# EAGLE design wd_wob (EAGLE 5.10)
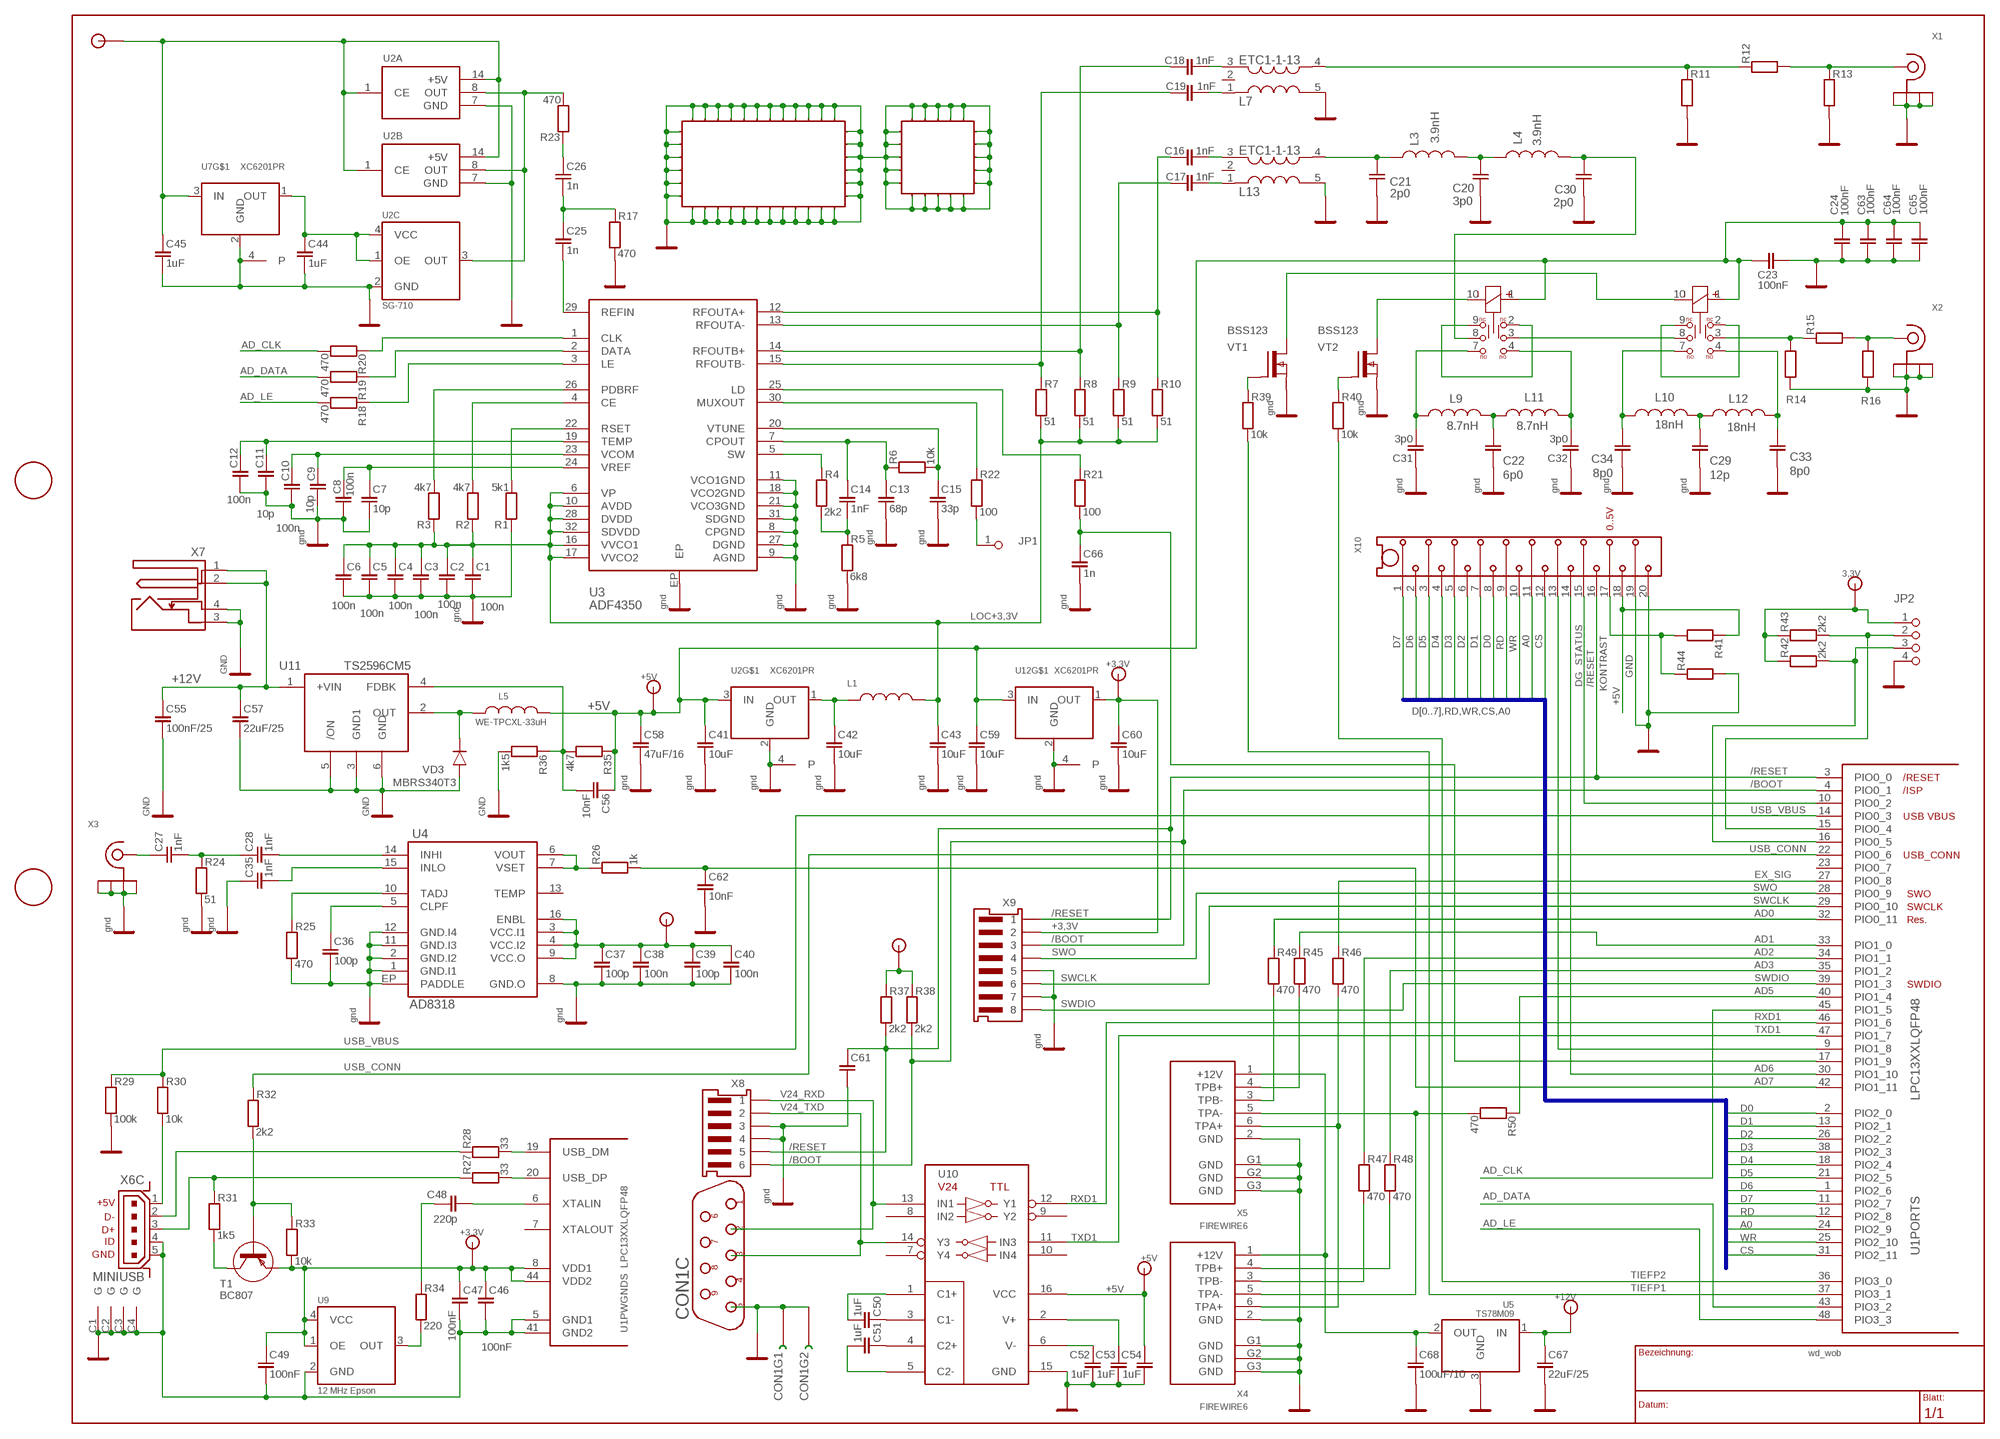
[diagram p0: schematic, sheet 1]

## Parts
C1  100n  SMD-0603  [SOT-0603]
C2  100n  SMD-0603  [SOT-0603]
C3  100n  SMD-0603  [SOT-0603]
C4  100n  SMD-0603  [SOT-0603]
C5  100n  SMD-0603  [SOT-0603]
C6  100n  SMD-0603  [SOT-0603]
C7  10p  SMD-0603  [SOT-0603]
C8  100n  SMD-0603  [SOT-0603]
C9  10p  SMD-0603  [SOT-0603]
C10  100n  SMD-0603  [SOT-0603]
C11  10p  SMD-0603  [SOT-0603]
C12  100n  SMD-0603  [SOT-0603]
C13  68p  SMD-0603  [SOT-0603]
C14  1nF  SMD-0603  [SOT-0603]
C15  33p  SMD-0603  [SOT-0603]
C16  1nF  SMD-0603  [SOT-0603]
C17  1nF  SMD-0603  [SOT-0603]
C18  1nF  SMD-0603  [SOT-0603]
C19  1nF  SMD-0603  [SOT-0603]
C20  3p0  SMD-0603  [SOT-0603]
C21  2p0  SMD-0603  [SOT-0603]
C22  6p0  SMD-0603  [SOT-0603]
C23  100nF  SMD-0603  [SOT-0603]
C24  100nF  SMD-0603  [SOT-0603]
C25  1n  SMD-0603  [SOT-0603]
C26  1n  SMD-0603  [SOT-0603]
C27  1nF  SMD-0603  [SOT-0603]
C28  1nF  SMD-0603  [SOT-0603]
C29  12p  SMD-0603  [SOT-0603]
C30  2p0  SMD-0603  [SOT-0603]
C31  3p0  SMD-0603  [SOT-0603]
C32  3p0  SMD-0603  [SOT-0603]
C33  8p0  SMD-0603  [SOT-0603]
C34  8p0  SMD-0603  [SOT-0603]
C35  1nF  SMD-0603  [SOT-0603]
C36  100p  SMD-0603  [SOT-0603]
C37  100p  SMD-0603  [SOT-0603]
C38  100n  SMD-0603  [SOT-0603]
C39  100p  SMD-0603  [SOT-0603]
C40  100n  SMD-0603  [SOT-0603]
C41  10uF  SMD-0805  [SOT-0805]
C42  10uF  SMD-0805  [SOT-0805]
C43  10uF  SMD-0805  [SOT-0805]
C44  1uF  SMD-0805  [SOT-0805]
C45  1uF  SMD-0805  [SOT-0805]
C46  100nF  SMD-0603  [SOT-0603]
C47  100nF  SMD-0603  [SOT-0603]
C48  220p  SMD-0603  [SOT-0603]
C49  100nF  SMD-0603  [SOT-0603]
C50  1uF  SMD-0805  [SOT-0805]
C51  1uF  SMD-0805  [SOT-0805]
C52  1uF  SMD-0805  [SOT-0805]
C53  1uF  SMD-0805  [SOT-0805]
C54  1uF  SMD-0805  [SOT-0805]
C55  100nF/25  SMD-0805  [SOT-0805]
C56  10nF  SMD-0805  [SOT-0805]
C57  22uF/25  SMD-1210  [SOT-1210]
C58  47uF/16  SMD-1210  [SOT-1210]
C59  10uF  SMD-0805  [SOT-0805]
C60  10uF  SMD-0805  [SOT-0805]
C61  SMD-0603  [SOT-0603]
C62  10nF  SMD-0603  [SOT-0603]
C63  100nF  SMD-0603  [SOT-0603]
C64  100nF  SMD-0603  [SOT-0603]
C65  100nF  SMD-0603  [SOT-0603]
C66  1n  SMD-0603  [SOT-0603]
C67  22uF/25  SMD-1210  [SOT-1210]
C68  100uF/10  SMD-1210  [SOT-1210]
CON1  DB9M/90  [DZ09M/90]
JP1  PINHD-1X1  [1X01]
JP2  PINHD-1X4  [1X04]
L1  SMD-0805  [SMD-0805]
L3  3.9nH  SMD-0603  [SMD-0603]
L4  3.9nH  SMD-0603  [SMD-0603]
L5  WE-TPCXL-33uH  WE-TPCXL  [WE-TPCXL]
L7  ETC1-1-13  [ETC1-1-13]
L9  8.7nH  SMD-0603  [SMD-0603]
L10  18nH  SMD-0603  [SMD-0603]
L11  8.7nH  SMD-0603  [SMD-0603]
L12  18nH  SMD-0603  [SMD-0603]
L13  ETC1-1-13  [ETC1-1-13]
R1  5k1  SMD-0603  [SMD-0603]
R2  4k7  SMD-0603  [SMD-0603]
R3  4k7  SMD-0603  [SMD-0603]
R4  2k2  SMD-0603  [SMD-0603]
R5  6k8  SMD-0603  [SMD-0603]
R6  10k  SMD-0603  [SMD-0603]
R7  51  SMD-0603  [SMD-0603]
R8  51  SMD-0603  [SMD-0603]
R9  51  SMD-0603  [SMD-0603]
R10  51  SMD-0603  [SMD-0603]
R11  SMD-0603  [SMD-0603]
R12  SMD-0603  [SMD-0603]
R13  SMD-0603  [SMD-0603]
R14  SMD-0603  [SMD-0603]
R15  SMD-0603  [SMD-0603]
R16  SMD-0603  [SMD-0603]
R17  470  SMD-0603  [SMD-0603]
R18  470  SMD-0603  [SMD-0603]
R19  470  SMD-0603  [SMD-0603]
R20  470  SMD-0603  [SMD-0603]
R21  100  SMD-0603  [SMD-0603]
R22  100  SMD-0603  [SMD-0603]
R23  470  SMD-0603  [SMD-0603]
R24  51  SMD-0603  [SMD-0603]
R25  470  SMD-0603  [SMD-0603]
R26  1k  SMD-0603  [SMD-0603]
R27  33  SMD-0603  [SMD-0603]
R28  33  SMD-0603  [SMD-0603]
R29  100k  SMD-0603  [SMD-0603]
R30  10k  SMD-0603  [SMD-0603]
R31  1k5  SMD-0603  [SMD-0603]
R32  2k2  SMD-0603  [SMD-0603]
R33  10k  SMD-0603  [SMD-0603]
R34  220  SMD-0603  [SMD-0603]
R35  4k7  SMD-0805  [SMD-0805]
R36  1k5  SMD-0805  [SMD-0805]
R37  2k2  SMD-0603  [SMD-0603]
R38  2k2  SMD-0603  [SMD-0603]
R39  10k  SMD-0603  [SMD-0603]
R40  10k  SMD-0603  [SMD-0603]
R41  SMD-0603  [SMD-0603]
R42  2k2  SMD-0603  [SMD-0603]
R43  2k2  SMD-0603  [SMD-0603]
R44  SMD-0603  [SMD-0603]
R45  470  SMD-0603  [SMD-0603]
R46  470  SMD-0603  [SMD-0603]
R47  470  SMD-0603  [SMD-0603]
R48  470  SMD-0603  [SMD-0603]
R49  470  SMD-0603  [SMD-0603]
R50  470  SMD-0603  [SMD-0603]
REL1  Pollin  TQ-RELAIS  [TQ-RELAI]
REL2  Pollin  TQ-RELAIS  [TQ-RELAI]
S1  Shield-Gen  S31-62  [AK31X62]
S2  Shield-Det  S25-25  [AK25X25]
T1  BC807  BC807-40  [SOT-23]
U1  LPC13XXLQFP48  [LQFP48]
U2  XC6201PR  XC6201-PR  [SOT89]
U2A  QU-OSZ14  [OSC]
U2B  QU-OSZ8  [OSC-KURZ]
U2C  SG-710  [SG710]
U3  ADF4350  ADF4350CP-32-2  [CP32-2]
U4  AD8318  [CP16-4]
U5  TS78M09  TS78MXX  [DPAK]
U7  XC6201PR  XC6201-PR  [SOT89]
U9  12 MHz Epson  SG-710  [SG710]
U10  MAX-232CWE  [SO-16W]
U11  TS2596CM5  [TO263-5L]
U12  XC6201PR  XC6201-PR  [SOT89]
VD3  MBRS340T3  [SMC]
VT1  BSS123  [SOT-23]
VT2  BSS123  [SOT-23]
X1  SMA-EDGE'KANTE'  [SMA-EDGE]
X2  SMA-EDGE'KANTE'  [SMA-EDGE]
X3  SMA-EDGE'KANTE'  [SMA-EDGE]
X4  FIREWIRE6  [IEEE1394-6V]
X5  FIREWIRE6  [IEEE1394-6V]
X6  MINIUSB  [UX60A-MB-5SY]
X7  DC-10-XX  [DC-10-XX]
X8  LUMBG6  [LUMBG6]
X9  LUMBG8  [LUMBG8]
X10  MICMATCH20  [MIMA20]

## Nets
+3,3V: C46.2 C47.2 C49.2 C60.2 JP2.1 R33.1 R37.2 R38.2 R42.2 R43.2 T1.2(E) U1.8(PWGNDS:VDD1) U1.44(PWGNDS:VDD2) U9.1(OE) U9.4(VCC) U12.1(OUT) X9.2 ; supply symbol labelled 3,3V
+3,3V_XO: C44.2 U2C.1(OE) U2C.4(VCC) U7.1(OUT)
+5V: C23.2 C24.2 C37.2 C38.2 C39.2 C40.2 C41.2 C45.2 C54.2 C56.2 C58.2 C59.2 C63.2 C64.2 C65.2 L5.2 R35.2 R41.2 REL1.1(L+) REL2.1(L+) U2.3(IN) U2A.1(CE) U2A.14(+5V) U2B.1(CE) U2B.14(+5V) U4.3(VCC.I1) U4.4(VCC.I2) U4.9(VCC.O) U4.16(ENBL) U7.3(IN) U10.16(VCC) U12.3(IN) X10.18
+12V: C55.2 C57.2 C67.2 U5.1(IN) U11.1(+VIN) X7.1 X7.2
/BOOT: R38.1 U1.4(PORTS:PIO0_1) X8.6 X9.3
/RESET: C61.2 R37.1 U1.3(PORTS:PIO0_0) X8.5 X9.1 X10.16
A0: U1.24(PORTS:PIO2_9) X10.11
AD0: R49.2 U1.32(PORTS:PIO0_11)
AD1: R45.2 U1.33(PORTS:PIO1_0)
AD2: R47.2 U1.34(PORTS:PIO1_1)
AD3: R48.2 U1.35(PORTS:PIO1_2)
AD5: R50.2 U1.40(PORTS:PIO1_4)
AD6: U1.30(PORTS:PIO1_10) X10.14
AD7: C62.2 R26.1 U1.42(PORTS:PIO1_11)
AD_CLK: R20.1 U1.45(PORTS:PIO1_5)
AD_DATA: R19.1 U1.43(PORTS:PIO3_2)
AD_LE: R18.1 U1.48(PORTS:PIO3_3)
CS: U1.31(PORTS:PIO2_11) X10.12
D0: U1.2(PORTS:PIO2_0) X10.8
D1: U1.13(PORTS:PIO2_1) X10.7
D2: U1.26(PORTS:PIO2_2) X10.6
D3: U1.38(PORTS:PIO2_3) X10.5
D4: U1.18(PORTS:PIO2_4) X10.4
D5: U1.21(PORTS:PIO2_5) X10.3
D6: U1.1(PORTS:PIO2_6) X10.2
D7: U1.11(PORTS:PIO2_7) X10.1
DG_STATUS: U1.10(PORTS:PIO0_2) X10.15
EX_SIG: R46.2 U1.27(PORTS:PIO0_8)
F_REF: C26.2 R23.2
GND: C1.1 C2.1 C3.1 C4.1 C5.1 C6.1 C7.1 C8.1 C9.1 C10.1 C11.1 C12.1 C13.1 C15.1 C20.1 C21.1 C22.2 C23.1 C24.1 C29.2 C30.2 C31.2 C32.2 C33.2 C34.2 C35.2 C36.1 C37.1 C38.1 C39.1 C40.1 C41.1 C42.1 C43.1 C44.1 C45.1 C46.1 C47.1 C49.1 C52.1 C53.1 C54.1 C55.1 C57.1 C58.1 C59.1 C60.1 C61.1 C62.1 C63.1 C64.1 C65.1 C66.1 C67.1 C68.1 CON1.5 CON1.G1 CON1.G2 JP2.4 L7.5 L13.5 R1.2 R5.1 R11.1 R13.1 R14.1 R16.1 R17.1 R24.1 R25.1 R29.1 R36.1 R44.1 S1.1 S1.2 S1.3 S1.4 S1.5 S1.6 S1.7 S1.8 S1.9 S1.10 S1.11 S1.12 S1.13 S1.14 S1.15 S1.16 S1.17 S1.18 S1.19 S1.20 S1.21 S1.22 S1.23 S1.24 S1.25 S1.26 S1.27 S1.28 S1.29 S1.30 S1.31 S1.32 S1.33 S1.34 S1.35 S1.36 S2.1 S2.2 S2.3 S2.4 S2.5 S2.6 S2.7 S2.8 S2.9 S2.10 S2.11 S2.12 S2.13 S2.14 S2.15 S2.16 S2.17 S2.18 S2.19 S2.20 U1.5(PWGNDS:GND1) U1.41(PWGNDS:GND2) U2.2(GND) U2.4(P) U2A.7(GND) U2B.7(GND) U2C.2(GND) U3.8(CPGND) U3.9(AGND) U3.11(VCO1GND) U3.18(VCO2GND) U3.21(VCO3GND) U3.27(DGND) U3.31(SDGND) U3.EP U4.1(GND.I1) U4.2(GND.I2) U4.8(GND.O) U4.11(GND.I3) U4.12(GND.I4) U4.EP(PADDLE) U5.3(GND) U7.2(GND) U7.4(P) U9.2(GND) U10.15(GND) U11.3(GND1) U11.5(/ON) U11.6(GND) U12.2(GND) U12.4(P) VD3.A VT1.2(S) VT2.2(S) X1.GND@1(GND) X1.GND@2(GND) X1.GND@3(GND) X1.GND@4(GND) X2.GND@1(GND) X2.GND@2(GND) X2.GND@3(GND) X2.GND@4(GND) X3.GND@1(GND) X3.GND@2(GND) X3.GND@3(GND) X3.GND@4(GND) X4.2(GND) X4.G1(GND) X4.G2(GND) X4.G3(GND) X5.2(GND) X5.G1(GND) X5.G2(GND) X5.G3(GND) X6.4 X6.5 X6.C1(G) X6.C2(G) X6.C3(G) X6.C4(G) X7.3 X7.4 X8.3 X8.4 X9.5 X9.7 X10.19 X10.20 ; supply symbol labelled gnd
KONTRAST: R41.1 R44.2 X10.17
LOC+3,3V: C1.2 C2.2 C3.2 C4.2 C5.2 C6.2 C43.2 L1.2 R2.2 R3.2 R7.1 R8.1 R9.1 R10.1 U3.6(VP) U3.10(AVDD) U3.16(VVCO1) U3.17(VVCO2) U3.28(DVDD) U3.32(SDVDD)
N$1: R18.2 U3.3(LE)
N$2: C7.2 C8.2 U3.24(VREF)
N$3: C9.2 C10.2 U3.23(VCOM)
N$4: C11.2 C12.2 U3.19(TEMP)
N$5: R1.1 U3.22(RSET)
N$6: C19.2 R7.2 U3.15(RFOUTB-)
N$7: R2.1 U3.4(CE)
N$8: R3.1 U3.26(PDBRF)
N$9: C15.2 R6.1 U3.20(VTUNE)
N$10: C14.1 R4.1 R5.2
N$11: R4.2 U3.5(SW)
N$12: C13.2 C14.2 R6.2 U3.7(CPOUT)
N$13: C18.2 R8.2 U3.14(RFOUTB+)
N$14: R19.2 U3.2(DATA)
N$15: R20.2 U3.1(CLK)
N$16: C17.2 R9.2 U3.13(RFOUTA-)
N$17: C16.2 R10.2 U3.12(RFOUTA+)
N$18: C18.1 L7.3
N$19: C19.1 L7.1
N$20: C16.1 L13.3
N$21: C17.1 L13.1
N$22: L7.4 R11.2 R12.2
N$23: R12.1 R13.2 X1.A
N$24: C21.2 L3.1 L13.4
N$25: C20.2 L3.2 L4.1
N$26: C30.1 L4.2 REL1.8(M2)
N$27: R15.1 R16.2 X2.A
N$28: R14.2 R15.2 REL2.3(M1)
N$29: REL2.2(NC1) REL2.9(NC2)
N$30: C33.1 L12.2 REL2.4(NO1)
N$31: C34.1 L10.1 REL2.7(NO2)
N$32: REL1.3(M1) REL2.8(M2)
N$33: C32.1 L11.2 REL1.4(NO1)
N$34: C29.1 L10.2 L12.1
N$35: C22.1 L9.2 L11.1
N$36: C31.1 L9.1 REL1.7(NO2)
N$37: REL1.2(NC1) REL1.9(NC2)
N$38: REL1.10(L-) VT2.3(D)
N$39: REL2.10(L-) VT1.3(D)
N$40: C25.1 U3.29(REFIN)
N$41: C25.2 C26.1 R17.2
N$42: R21.2 U3.25(LD)
N$43: R22.2 U3.30(MUXOUT)
N$44: R23.1 U2A.8(OUT) U2B.8(OUT) U2C.3(OUT)
N$45: C27.2 X3.A
N$46: C27.1 C28.2 R24.2
N$47: C28.1 U4.14(INHI)
N$48: C35.1 U4.15(INLO)
N$49: C36.2 U4.5(CLPF)
N$50: R25.2 U4.10(TADJ)
N$51: R26.2 U4.6(VOUT) U4.7(VSET)
N$52: C42.2 L1.1 U2.1(OUT)
N$53: R27.2 R31.2 X6.3
N$54: R28.2 X6.2
N$55: R30.1 X6.1
N$56: R28.1 U1.19(PWGNDS:USB_DM)
N$57: R27.1 U1.20(PWGNDS:USB_DP)
N$58: R31.1 T1.3(C)
N$59: R32.1 R33.2 T1.1(B)
N$60: C48.1 U1.6(PWGNDS:XTALIN)
N$61: C48.2 R34.2
N$62: R34.1 U9.3(OUT)
N$63: C50.1 U10.1(C1+)
N$64: C50.2 U10.3(C1-)
N$65: C51.2 U10.4(C2+)
N$66: C51.1 U10.5(C2-)
N$67: C52.2 U10.6(V-)
N$68: C53.2 U10.2(V+)
N$69: C66.2 R21.1 U1.17(PORTS:PIO1_9)
N$70: JP1.1 R22.1
N$71: R39.2 VT1.1(G)
N$72: R40.2 VT2.1(G)
N$73: L5.1 U11.2(OUT) VD3.K
N$74: C56.1 R35.1 R36.2 U11.4(FDBK)
N$75: JP2.2 R43.1 U1.15(PORTS:PIO0_4)
N$76: JP2.3 R42.1 U1.16(PORTS:PIO0_5)
N$77: U1.9(PORTS:PIO1_8) X10.13
N$78: R48.1 X4.4(TPB+)
N$79: R47.1 X4.3(TPB-)
N$80: R45.1 X5.4(TPB+)
N$81: R49.1 X5.3(TPB-)
N$82: R46.1 X4.6(TPA+) X5.6(TPA+)
N$83: R50.1 X4.5(TPA-) X5.5(TPA-)
OUT: C68.2 U5.2(OUT) X4.1(+12V) X5.1(+12V)
RD: U1.12(PORTS:PIO2_8) X10.9
RXD1: U1.46(PORTS:PIO1_6) U10.12(Y1)
SWCLK: U1.29(PORTS:PIO0_10) X9.6
SWDIO: U1.39(PORTS:PIO1_3) X9.8
SWO: U1.28(PORTS:PIO0_9) X9.4
TIEFP1: R39.1 U1.37(PORTS:PIO3_1)
TIEFP2: R40.1 U1.36(PORTS:PIO3_0)
TXD1: U1.47(PORTS:PIO1_7) U10.11(IN3)
USB_CONN: R32.2 U1.22(PORTS:PIO0_6)
USB_VBUS: R29.2 R30.2 U1.14(PORTS:PIO0_3)
V24_RXD: CON1.2 U10.13(IN1) X8.1
V24_TXD: CON1.3 U10.14(Y3) X8.2
WR: U1.25(PORTS:PIO2_10) X10.10
Unconnected: CON1.1 CON1.4 CON1.6 CON1.7 CON1.8 CON1.9 L7.2 L13.2 U1.7(PWGNDS:XTALOUT) U1.23(PORTS:PIO0_7) U4.13(TEMP) U10.7(Y4) U10.8(IN2) U10.9(Y2) U10.10(IN4)

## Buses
D[0..7],RD,WR,CS,A0

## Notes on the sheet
- 0..5V

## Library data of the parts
C1-C40 C46-C49 C61-C66 = C_KERAM:SMD-0603
C41-C45 C50-C56 C59 C60 = C_KERAM:SMD-0805
C57 C58 C67 C68 = C_KERAM:SMD-1210
CON1 = Z_CONNEC:DB9M/90
JP1 = PINHD-Q:PINHD-1X1
JP2 = PINHD-Q:PINHD-1X4
L1 = L:SMD-0805
L3 L4 L9-L12 = L:SMD-0603
L5 = L:WE-TPCXL
L7 L13 = HAMRAD:ETC1-1-13: MACOM Transmission-Line Balun 4.5 - 3000 MHz
R1-R34 R37-R50 = R:SMD-0603
R35 R36 = R:SMD-0805
REL1 REL2 = HAMRAD:TQ-RELAIS
S1 = SHIELDS:S31-62
S2 = SHIELDS:S25-25
T1 = TR_PNP:BC807-40
U1 = philips:LPC13XX
U2 U7 U12 = TOREX:XC6201-PR
U2A = Z_SPECIA:QU-OSZ14
U2B = Z_SPECIA:QU-OSZ8
U2C U9 = SEIK_EPS:SG-710
U3 = ANALOG_D:ADF4350: 4.4 GHz Synthesizer mit integriertem VCO
U4 = ANALOG_D:AD8318
U5 = TSC:TS78MXX
U10 = MAXIM:MAX-232CWE
U11 = TSC:TS2596CM5
VD3 = DIODEN:MBRS340T3
VT1 VT2 = TR_FET:BSS123
X1-X3 = HAMRAD:SMA-EDGE
X4 X5 = Z_CONNEC:FIREWIRE6
X6 = mini-usb:MINIUSB
X7 = Z_CONNEC:DC-10-XX
X8 = Z_CONNEC:LUMBG6
X9 = Z_CONNEC:LUMBG8
X10 = TYCO:MICMATCH20

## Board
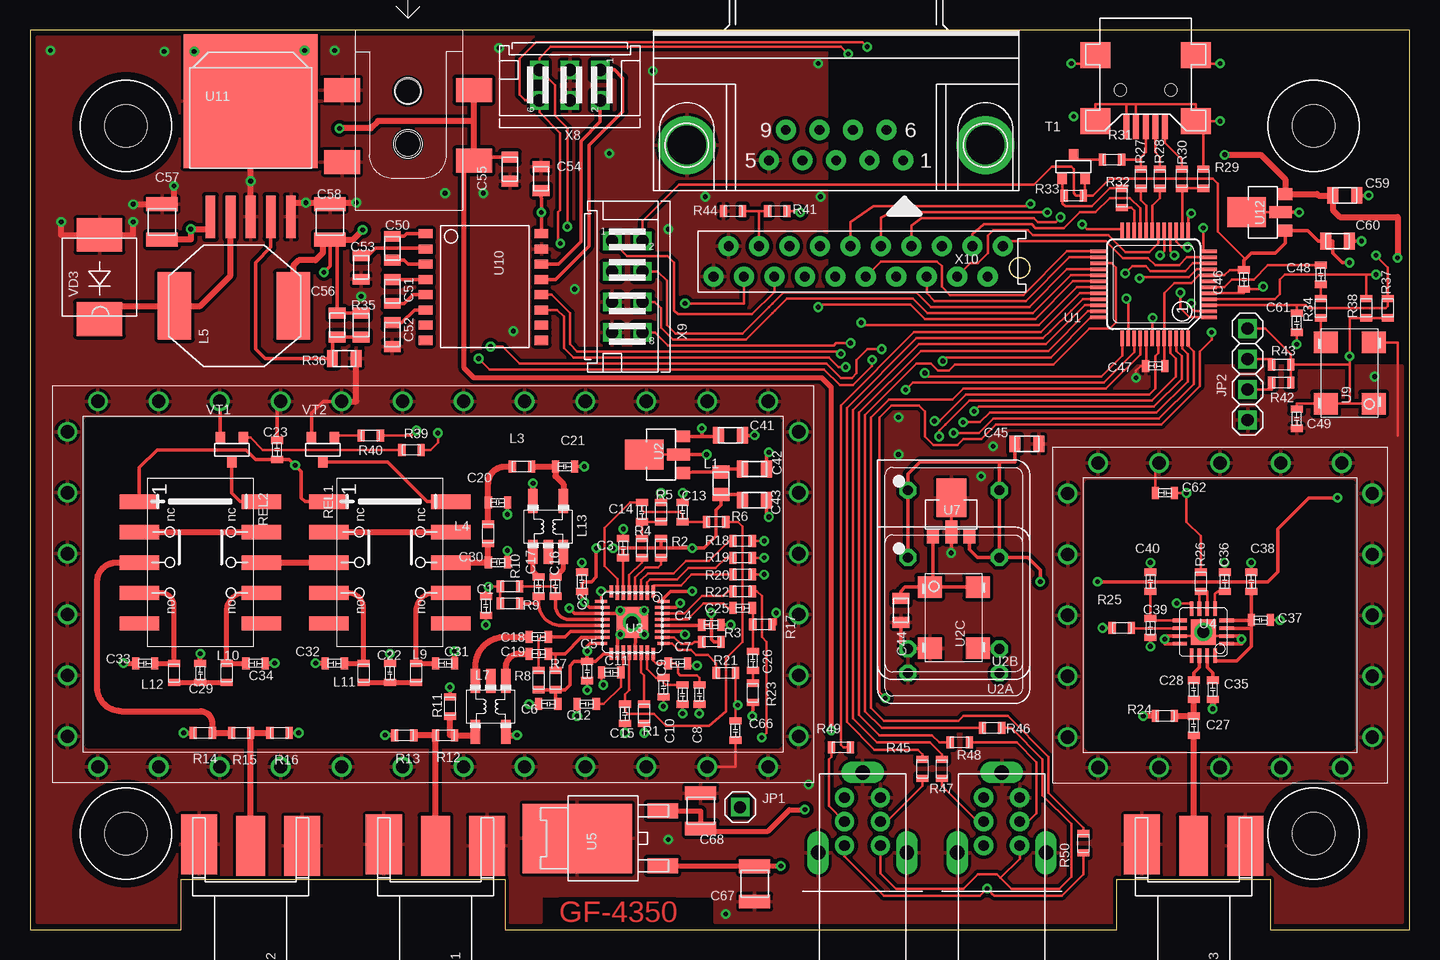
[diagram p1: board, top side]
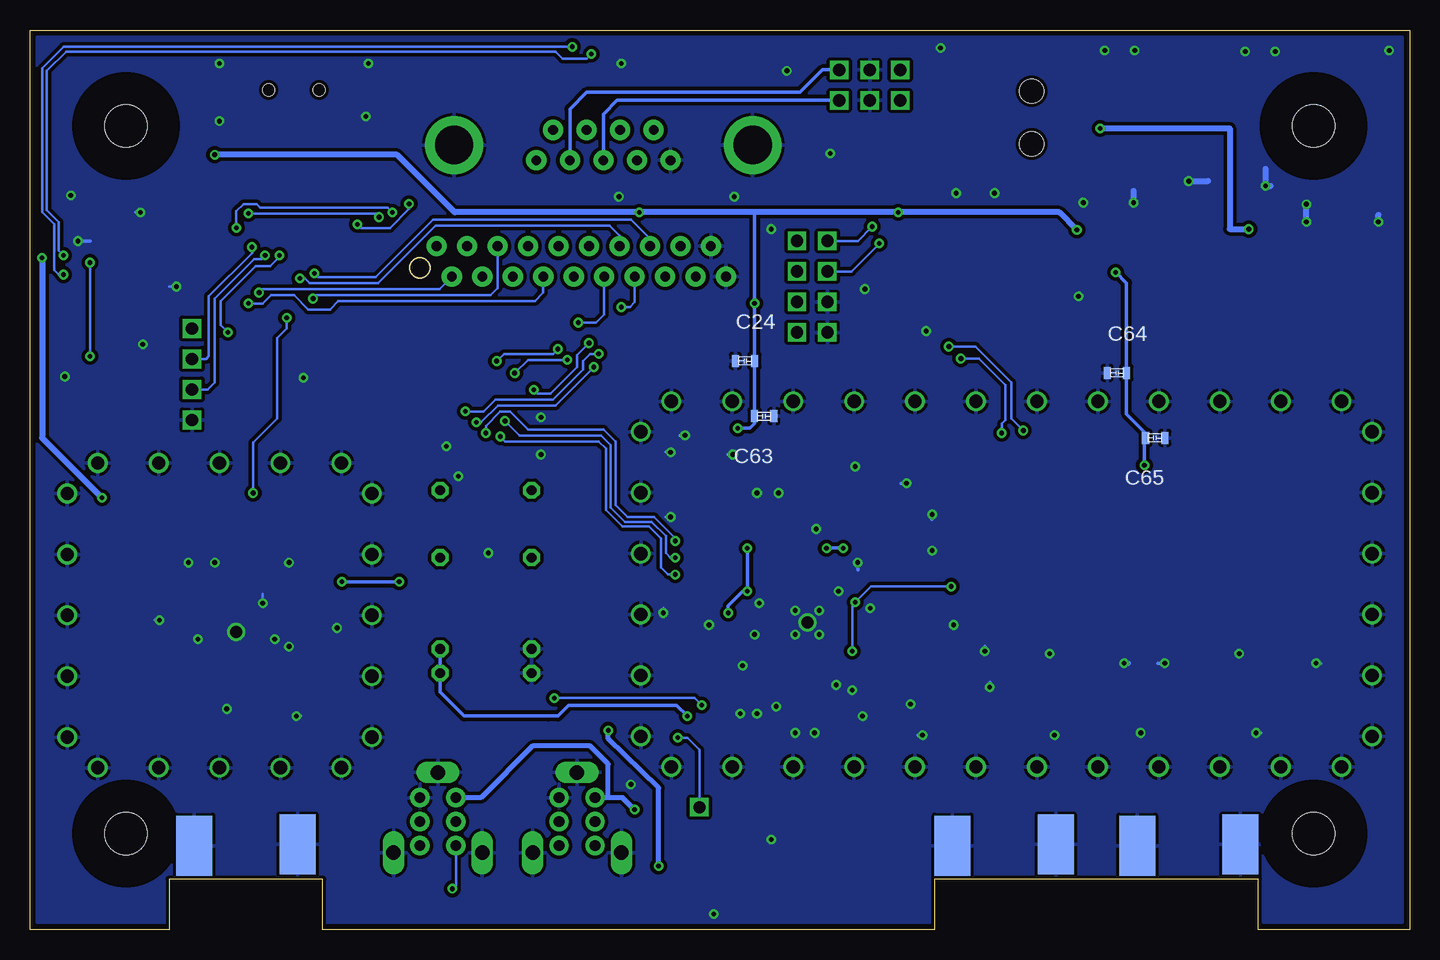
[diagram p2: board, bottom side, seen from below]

Size 115 x 75 mm. Coordinates in mm from the lower left corner, seen from the top.
Outline: 0,0 12.6,0 12.6,4.2 39.6,4.2 39.6,0 90.6,0 90.6,4.2 103.4,4.2 103.4,0 115,0 115,75 0,75 0,0
Copper layers (1*16): Top 0.035mm / dielectric 1.5mm / Bottom 0.035mm
Design rules "default": minimum track width 0.15mm, minimum drill 0.3mm, track to track 0.15mm, track to pad 0.15mm, pad to pad 0.15mm, via to via 0.15mm, smd to smd 0mil, copper to edge 0.15mm, drill to drill 0.15mm, minimum pad ring 0.15mm, minimum via ring 0.15mm, stop-mask expansion 4mil, vias tented up to drill 0mil, thermal gap 10mil
tRestrict: area 4.8,15.4 to 62.4,42.4; area 88.2,15.2 to 110.2,37.2

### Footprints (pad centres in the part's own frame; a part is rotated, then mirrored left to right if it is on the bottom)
SOT-0603 = smd 0.6 x 1: 1 -0.8,0; 2 0.8,0
SOT-0805 = smd 0.914 x 1.397: 1 -0.991,0; 2 0.991,0
SOT-1210 = smd 1.143 x 2.591: 1 -1.473,0; 2 1.473,0
DZ09M/90 = drill 0.813 pad 1.676 round: 1 5.588,-1.27; 2 2.794,-1.27; 3 0,-1.27; 4 -2.794,-1.27; 5 -5.588,-1.27; 6 4.191,1.27; 7 1.397,1.27; 8 -1.397,1.27; 9 -4.191,1.27 | drill 3.2 pad 4.064 round: G1 12.446,0; G2 -12.446,0
1X01 = drill 1.016 pad 1.524 square: 1 0,0
1X04 = drill 1.016 pad 1.575 square: 1 -3.81,0; 2 -1.27,0; 3 1.27,0; 4 3.81,0
SMD-0805 = smd 1.092 x 1.397: 1 -0.94,0; 2 0.94,0
SMD-0603 = smd 0.6 x 1: 1 -0.8,0; 2 0.8,0
WE-TPCXL = smd 5.588 x 2.794: 1 0,4.953; 2 0,-4.953
ETC1-1-13 = smd 0.8 x 2: 1 1.27,2.14; 2 0,2.14; 3 -1.27,2.14; 4 -1.27,-2.14; 5 1.27,-2.14
SMD-0805' = smd 0.914 x 1.397: 1 -0.991,0; 2 0.991,0
TQ-RELAI = smd 1.2 x 3.3: 1 -5.08,-5.08; 2 -2.54,-5.08; 3 0,-5.08; 4 2.54,-5.08; 5 5.08,-5.08; 6 5.08,5.08; 7 2.54,5.08; 8 0,5.08; 9 -2.54,5.08; 10 -5.08,5.08
AK31X62 = drill 1.1 pad 1.6 round: 1 -15.24,-27.94; 2 -15.24,-2.54; 3 -15.24,2.54; 4 -15.24,7.62; 5 -15.24,27.94; 6 -12.7,30.48; 7 -2.54,30.48; 8 2.54,30.48; 9 -15.24,22.86; 10 12.7,30.48; 11 15.24,27.94; 12 15.24,7.62; 13 15.24,2.54; 14 15.24,-2.54; 15 15.24,-27.94; 16 12.7,-30.48; 17 -15.24,17.78; 18 2.54,-30.48; 19 -2.54,-30.48; 20 -12.7,-30.48; 21 15.24,12.7; 22 -15.24,12.7; 23 -15.24,-7.62; 24 15.24,-7.62; 25 15.24,22.86; 26 15.24,17.78; 27 -15.24,-12.7; 28 -15.24,-17.78; 29 15.24,-12.7; 30 15.24,-17.78; 31 15.24,-22.86; 32 -15.24,-22.86; 33 -7.62,30.48; 34 7.62,30.48; 35 -7.62,-30.48; 36 7.62,-30.48
AK25X25 = drill 1.1 pad 1.6 round: 1 -12.7,-10.16; 2 -12.7,-5.08; 3 -12.7,0; 4 -12.7,5.08; 5 -12.7,10.16; 6 -10.16,12.7; 7 -5.08,12.7; 8 0,12.7; 9 5.08,12.7; 10 10.16,12.7; 11 12.7,10.16; 12 12.7,5.08; 13 12.7,0; 14 12.7,-5.08; 15 12.7,-10.16; 16 10.16,-12.7; 17 5.08,-12.7; 18 0,-12.7; 19 -5.08,-12.7; 20 -10.16,-12.7
SOT-23 = smd 0.787 x 0.889: 1 0.94,1.016; 2 -0.94,1.016; 3 0,-1.016
LQFP48 = smd 0.279 x 1.27: 1 -2.75,-4.5; 2 -2.25,-4.5; 3 -1.75,-4.5; 4 -1.25,-4.5; 5 -0.75,-4.5; 6 -0.25,-4.5; 7 0.25,-4.5; 8 0.75,-4.5; 9 1.25,-4.5; 10 1.75,-4.5; 11 2.25,-4.5; 12 2.75,-4.5; 25 2.75,4.75; 26 2.25,4.75; 27 1.75,4.75; 28 1.25,4.75; 29 0.75,4.75; 30 0.25,4.75; 31 -0.25,4.75; 32 -0.75,4.75; 33 -1.25,4.75; 34 -1.75,4.75; 35 -2.25,4.75; 36 -2.75,4.75 | smd 1.27 x 0.279: 13 4.5,-2.75; 14 4.5,-2.25; 15 4.5,-1.75; 16 4.5,-1.25; 17 4.5,-0.75; 18 4.5,-0.25; 19 4.5,0.25; 20 4.5,0.75; 21 4.5,1.25; 22 4.5,1.75; 23 4.5,2.25; 24 4.5,2.75; 37 -4.5,2.75; 38 -4.5,2.25; 39 -4.5,1.75; 40 -4.5,1.25; 41 -4.5,0.75; 42 -4.5,0.25; 43 -4.5,-0.25; 44 -4.5,-0.75; 45 -4.5,-1.25; 46 -4.5,-1.75; 47 -4.5,-2.25; 48 -4.5,-2.75
SOT89 = smd 0.991 x 1.194: 1 -1.524,-1.829; 3 1.524,-1.829 | smd 0.991 x 1.905: 2 0,-1.448 | smd 2.5 x 3.2: 4 0,1.4
OSC = drill 0.813 pad 1.397 octagon: 1 -7.62,-3.81; 7 7.62,-3.81; 8 7.62,3.81; 14 -7.62,3.81
OSC-KURZ = drill 0.813 pad 1.397 octagon: 1 -3.81,-3.81; 7 3.81,-3.81; 8 3.81,3.81; 14 -3.81,3.81
SG710 = smd 1.8 x 2: 1 -2.55,-2; 2 2.55,-2; 3 2.55,2; 4 -2.55,2
CP32-2 = smd 1 x 0.28: 1 -2.6,1.75; 8 -2.6,-1.75; 17 2.6,-1.75; 24 2.6,1.75 | smd 1.2 x 0.28: 2 -2.5,1.25; 3 -2.5,0.75; 4 -2.5,0.25; 5 -2.5,-0.25; 6 -2.5,-0.75; 7 -2.5,-1.25; 18 2.5,-1.25; 19 2.5,-0.75; 20 2.5,-0.25; 21 2.5,0.25; 22 2.5,0.75; 23 2.5,1.25 | smd 0.28 x 1: 9 -1.75,-2.6; 16 1.75,-2.6; 25 1.75,2.6; 32 -1.75,2.6 | smd 0.28 x 1.2: 10 -1.25,-2.5; 11 -0.75,-2.5; 12 -0.25,-2.5; 13 0.25,-2.5; 14 0.75,-2.5; 15 1.25,-2.5; 26 1.25,2.5; 27 0.75,2.5; 28 0.25,2.5; 29 -0.25,2.5; 30 -0.75,2.5; 31 -1.25,2.5 | smd 2.6 x 2.6: EP 0,0
CP16-4 = smd 1.2 x 0.3: 1 -1.95,0.975; 2 -1.95,0.325; 3 -1.95,-0.325; 4 -1.95,-0.975; 9 1.95,-0.975; 10 1.95,-0.325; 11 1.95,0.325; 12 1.95,0.975 | smd 0.3 x 1.2: 5 -0.975,-1.95; 6 -0.325,-1.95; 7 0.325,-1.95; 8 0.975,-1.95; 13 0.975,1.95; 14 0.325,1.95; 15 -0.325,1.95; 16 -0.975,1.95 | smd 2.1 x 2.1: EP 0,0
DPAK = smd 1.27 x 2.54: 1 -2.286,-2.032; 2 2.286,-2.032 | smd 5.8 x 9.1: 3 0,5.08
SO-16W = smd 0.762 x 1.143: 1 -3.81,-4.826; 2 -2.54,-4.826; 3 -1.27,-4.826; 4 0,-4.826; 5 1.27,-4.826; 6 2.54,-4.826; 7 3.81,-4.826; 8 5.08,-4.826; 9 5.08,4.826; 10 3.81,4.826; 11 2.54,4.826; 12 1.27,4.826; 13 0,4.826; 14 -1.27,4.826; 15 -2.54,4.826; 16 -3.81,4.826
TO263-5L = smd 0.813 x 3.556: 1 -3.353,-8.382; 2 -1.676,-8.382; 3 0,-8.382; 4 1.676,-8.382; 5 3.353,-8.382 | smd 11.176 x 11.176: 6 0,1.27
DRIL-3,5 = hole 3.556: 0,0
SMC = smd 2.794 x 3.81: A 3.505,0; K -3.505,0
SOT-23' = smd 0.787 x 0.889: 1 0.991,1.016; 2 -0.94,1.016; 3 0.025,-1.016
SMA-EDGE = smd 5 x 2.4: A 0,0 | smd 5 x 3: GND@1 0,4.3; GND@2 -0.1,-4.3 | smd 5 x 3 bottom: GND@3 0,4.3; GND@4 -0.1,-4.3
IEEE1394-6V = drill 0.9 pad 1.6 round: 1 4,1.5; 2 4,-1.5; 3 2,1.5; 4 2,-1.5; 5 0,1.5; 6 0,-1.5 | drill 1.2 long: G1 6.1,0; G2 -0.6,3.7; G3 -0.6,-3.7
UX60A-MB-5SY = smd 0.5 x 2: 1 -1.6,3.1; 2 -0.8,3.1; 3 0,3.1; 4 0.8,3.1; 5 1.6,3.1 | smd 2.5 x 2.2: C1 -4.2,2.6; C2 -4.2,-2.9; C3 4.2,-2.9; C4 4.2,2.6 | hole 1.016: -2.1,0; 2.1,0
DC-10-XX = smd 3 x 2: 1 5.5,-5.9; 2 5.5,0; 3 -5.5,0; 4 -5.5,-6 | hole 2: 0,-0.1; 0,-4.5
LUMBG6 = drill 1.016 pad 1.422 square: 1 -1.27,2.54; 2 1.27,2.54; 3 -1.27,0; 4 1.27,0; 5 -1.27,-2.54; 6 1.27,-2.54
LUMBG8 = drill 1.016 pad 1.422 square: 1 -1.27,3.81; 2 1.27,3.81; 3 -1.27,1.27; 4 1.27,1.27; 5 -1.27,-1.27; 6 1.27,-1.27; 7 -1.27,-3.81; 8 1.27,-3.81
MIMA20 = drill 0.813 pad 1.676 round: 1 0,1.27; 2 -1.27,-1.27; 3 -2.54,1.27; 4 -3.81,-1.27; 5 -5.08,1.27; 6 -6.35,-1.27; 7 -7.62,1.27; 8 -8.89,-1.27; 9 -10.16,1.27; 10 -11.43,-1.27; 11 -12.7,1.27; 12 -13.97,-1.27; 13 -15.24,1.27; 14 -16.51,-1.27; 15 -17.78,1.27; 16 -19.05,-1.27; 17 -20.32,1.27; 18 -21.59,-1.27; 19 -22.86,1.27; 20 -24.13,-1.27 | hole 1.676: 1.4,-0.53

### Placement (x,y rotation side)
C1  38,27 90 top
C2  46,29 270 top
C3  49.45,31.8 270 top
C4  56.8,25.4 180 top
C5  46.45,21.55 90 top
C6  43.2,18.8 0 top
C7  54,22.2 180 top
C8  55.8,19.6 90 top
C9  52.8,20.2 90 top
C10  54.4,19.6 90 top
C11  48.45,21.45 0 top
C12  46.4,18.8 0 top
C13  54.4,34.8 270 top
C14  51,34.8 90 top
C15  49.6,18 90 top
C16  43.8,28.6 270 top
C17  42.4,28.6 270 top
C18  42.4,24.4 0 top
C19  42.4,23 0 top
C20  39,35.6 180 top
C21  44.6,38.6 180 top
C22  30,21.4 90 top
C23  20.6,40 270 top
C24  55.4,47.4 0 bottom
C25  59.4,26.8 0 top
C26  60.25,22.4 270 top
C27  97,17 270 top
C28  97,20 270 top
C29  14.2,21.4 90 top
C30  39,30.6 0 top
C31  34.6,22.2 0 top
C32  25.4,22.2 180 top
C33  9.6,22.2 180 top
C34  18.8,22.2 0 top
C35  98.6,20 270 top
C36  99.6,29 270 top
C37  102.6,25.8 180 top
C38  101.8,29 270 top
C39  93.4,25.15 90 top
C40  93.4,29 270 top
C41  58.4,41.2 180 top
C42  60.4,38.4 180 top
C43  60.4,35.8 180 top
C44  72.6,26.6 90 top
C45  83.1,40.5 180 top
C46  101.2,54.2 90 top
C47  93.8,47 0 top
C48  107.6,54.6 270 top
C49  105.6,42.6 90 top
C50  30.2,56.8 270 top
C51  30.2,53.2 90 top
C52  30.2,49.6 90 top
C53  27.6,55.2 90 top
C54  42.6,62.6 270 top
C55  40,63.4 90 top
C56  25.6,50.4 90 top
C57  11,59 270 top
C58  25,59 270 top
C59  109.6,61.2 180 top
C60  109,57.4 180 top
C61  105.6,50.6 90 top
C62  94.6,36.4 0 top
C63  53.8,42.8 180 bottom
C64  24.4,46.4 0 bottom
C65  21.2,41 180 bottom
C66  58.8,16.6 90 top
C67  60.4,3.8 90 top
C68  55.9,9.9 270 top
CON1  67.2,65.4 0 top
JP1  59.2,10.2 0 top
JP2  101.5,46.3 270 top
L1  57.6,37.2 270 top
L3  41,38.6 180 top
L4  38.2,33 270 top
L5  17,52 90 top
L7  38.4,18.6 0 top
L9  32.2,21.4 270 top
L10  16.4,21.4 270 top
L11  27.8,21.4 90 top
L12  12,21.4 90 top
L13  43.2,33.6 180 top
R1  51.2,18 270 top
R2  52.6,31.8 90 top
R3  56.8,24 0 top
R4  51,31.8 270 top
R5  52.6,34.8 270 top
R6  57.2,34 180 top
R7  43.8,20.8 90 top
R8  42.4,20.8 90 top
R9  40,27.2 0 top
R10  40,28.6 0 top
R11  35,18.6 270 top
R12  34.6,16.2 0 top
R13  31.2,16.2 0 top
R14  14.4,16.4 0 top
R15  17.6,16.4 180 top
R16  20.8,16.4 180 top
R17  61.05,25.45 180 top
R18  59.4,32.4 180 top
R19  59.4,31 180 top
R20  59.4,29.6 180 top
R21  58,21.4 180 top
R22  59.4,28.2 180 top
R23  60.25,19.75 90 top
R24  94.6,17.8 0 top
R25  91,25.15 0 top
R26  97.6,29 270 top
R27  92.6,62.6 90 top
R28  94.2,62.6 90 top
R29  97.8,62.6 270 top
R30  96,62.6 270 top
R31  90.2,64.2 0 top
R32  91,61 270 top
R33  87,61.2 180 top
R34  107.6,51.8 90 top
R35  4k7  [SMD-0805']  27.6,50.4 90 top
R36  1k5  [SMD-0805']  26.2,47.6 180 top
R37  113.2,51.8 270 top
R38  111.4,51.8 270 top
R39  31.8,40 180 top
R40  28.4,41.2 180 top
R41  62.3,59.9 0 top
R42  104.3,45.6 0 top
R43  104.3,47.1 0 top
R44  58.6,59.9 0 top
R45  74.4,13.4 90 top
R46  80.2,16.8 180 top
R47  76,13.4 90 top
R48  77.5,15.6 180 top
R49  67.6,15.2 0 top
R50  87.8,7.2 90 top
REL1  30,30.6 270 top
REL2  14.2,30.6 270 top
S1  33.6,28.8 270 top
S2  99.2,26.2 0 top
T1  87,63.6 180 top
U1  93.8,53.8 90 top
U2  52.6,39.6 90 top
U2A  77,29 270 top
U2B  77,27.2 270 top
U2C  77,26 270 top
U3  50.2,25.6 270 top
U4  97.8,24.8 180 top
U5  50.7,7.6 90 top
U7  76.8,34.6 0 top
U9  110,46.4 90 top
U10  37.8,54.2 270 top
U11  18.4,67.8 0 top
U12  102.8,59.8 90 top
U$51  [DRIL-3,5]  107,8 0 top
U$52  [DRIL-3,5]  8,8 0 top
U$53  [DRIL-3,5]  107,67 0 top
U$54  [DRIL-3,5]  8,67 0 top
VD3  5.8,54.4 90 top
VT1  BSS123  [SOT-23']  16.8,40 0 top
VT2  BSS123  [SOT-23']  24.4,40 0 top
X1  33.8,7 270 top
X2  18.4,7 270 top
X3  97,7 270 top
X4  81,7 90 top
X5  69.4,7 90 top
X6  93,70 180 top
X7  31.5,70 0 top
X8  45,70.4 270 top
X9  49.8,53.6 0 top
X10  81.1,55.7 0 top

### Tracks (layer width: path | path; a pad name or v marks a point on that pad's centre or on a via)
+3,3V  (via drill 0.4 pad 0.8)
  Top 0.2: C49.2 105.6,43.85 U9.4 U9.1 110,43.85 110,47.1 | 110,47.1 v110,47.8 110,51 R38.2 R37.2 | C47.2 94.55,47.05 U1.44 94.55,53.05 95.4,53.9 96.8,53.9 97.45,54.55 U1.8 99.55,54.55 100,55 C46.2 | T1.2 87.94,61.2 R33.1 | R33.1 88.6,61.2 90,62.6 98.6,62.6 99,62.2 99,58.2 101.3,55.9 | R33.1 87.2,61.2 87,61.4 87,63.4 86.8,63.6 85.2,63.6 83.7,62.1 54.1,62.1 51.07,59.07 X9.2 | JP2.1 102.99,50.11 105.1,48 R43.2 | 110,47.1 R43.2 | R43.2 R42.2
  Top 0.3: C46.2 101.2,55.8 101.3,55.9 101.8,56.4 103.8,56.4 104.63,57.23 U12.1 106.52,58.28 107.4,57.4 C60.2 108.6,57.39 108.6,56.4 109.4,55.6 v110,55.6
  Bottom 0.2: v110,55.6 v110,47.8
+3,3V_XO
  Top 0.3: U7.1 75.28,28.55 U2C.1 | U2C.1 U2C.4 | U2C.1 72.95,28.55 72.6,28.2 C44.2
+5V  (via drill 0.4 pad 0.8)
  Top 0.2: 98.78,22.4 U4.16 | C37.2 101.8,25.77 | U4.9 93.4,25.77 C39.2 C40.2 | X10.18 59.51,52.2 v54.6,52.2 | R41.2 64.1,59.9 v64.2,59.8
  Top 0.3: 98.78,22.4 100.6,22.4 101.8,23.6 101.8,25.12 | 101.8,25.77 U4.4 | 101.8,25.12 U4.3 | 101.8,25.12 C37.2 C38.2 101.8,29 | 93.4,29 C40.2 | 101.8,29 93.4,29 | 93.4,29 v89,29 | U2B.1 U2A.1 73.19,37.99 74.2,39 80.81,39 | U2B.14 U2A.14 80.81,39 | v84.22,29 84.22,29.98 83.19,31.01 U2B.14 | U2B.14 78.99,31.01 78.32,31.68 U7.3 | C45.2 82.11,39 80.81,39 | 25.6,57.53 C56.2 R35.2 | C41.2 57.41,41.12 U2.3 56,41.12 v56,41.8 | U10.16 v42.63,59.8 42.63,60.4 C54.2 | 27.6,58.2 v27.73,58.33 | REL2.1 9.12,38.52 10.6,40 18,40 18.8,39.2 C23.2 21.6,39.2 v22.1,38.7 22.6,38.2 22.6,36 22.92,35.68 REL1.1 | v24.5,54.8 25,55.3 C58.2 | 101.8,29 103.2,29 104,29.8 104,33.4 106.6,36 v109,36
  Top 0.5: L5.2 21.95,55.35 22.4,55.8 23.8,55.8 24.4,56.4 24.4,57.53 C58.2 25.6,57.53 26.93,57.53 27.6,58.2 | v99.6,64.6 102.6,64.6 104.63,62.57 U12.3 107.28,61.32 107.4,61.2 C59.2 108.61,59.99 109.2,59.4 114,59.4 v114,56
  Bottom 0.3: v89,29 v84.22,29 | v22.1,38.7 22.1,41 | 22.1,41 22.1,41.5 23.6,43 C64.2 23.6,53.9 v24.5,54.8 | v56,41.8 55,41.8 54.6,42.2 C63.2 C24.2 v54.6,52.2 54.6,59.8 | 22.1,41 C65.2
  Bottom 0.5: v27.73,58.33 29.2,59.8 v42.63,59.8 54.6,59.8 v64.2,59.8 79.6,59.8 84.4,64.6 v99.6,64.6 | v114,56 114,41 v109,36
+12V  (via drill 0.4 pad 0.8)
  Top 0.2: C67.2 60.43,5.3
  Top 0.3: 37.1,64.39 C55.2
  Top 0.4: v66.8,16.6 66.8,45.2 66,46 37,46 36.2,46.8 36.2,64.39 | 60.43,5.3 v62.6,5.3 | U5.1 60.36,5.31 C67.2
  Top 0.5: C57.2 13.4,57.53 v13.4,58.4 15.05,58.4 U11.1 | v25.8,66.8 28.4,66.8 29,67.4 37,67.4 | 36.2,64.39 37.1,64.39 37.1,64.1 X7.1 37,67.4 | 37,67.4 X7.2
  Bottom 0.4: v66.8,16.6 66.8,15.9 62.6,11.8 v62.6,5.3
  Bottom 0.5: v13.4,58.4 15,58.4 15,66.8 v25.8,66.8
/BOOT  (via drill 0.4 pad 0.8)
  Top 0.2: v69.8,73.6 69.4,74 42.2,74 40.8,72.6 40.8,69.6 41.27,69.13 X8.6 42.46,68.14 44.2,66.4 44.2,60 44,59.8 44,57.4 v44.2,57.2 | U1.4 103.75,52.55 104.2,53 104.2,54.2 104.6,54.6 111.4,54.6 | v112.2,54.6 111.4,54.6 | 111.4,54.6 R38.1
  Bottom 0.2: v69.8,73.6 112.2,73.6 114,71.8 114,59.8 113,58.8 113,55 112.6,54.6 v112.2,54.6 | X9.3 46.53,54.87 v44.2,57.2
/RESET  (via drill 0.4 pad 0.8)
  Top 0.2: v68.2,73 67.6,73.6 43.4,73.6 42.46,72.66 X8.5 43.75,70.38 43.75,67.85 44.8,66.8 v44.8,58.6 | 105.6,52.05 106.35,52.05 106.6,51.8 113,51.8 113.2,52 R37.1 113.2,55.2 v112.2,56.2 | 105.6,52.05 U1.3 | 105.6,52.05 C61.2 | X10.16 62.05,53.15 60.2,51.3 54,51.3 53.7,51.6 53.7,55.6 53.15,56.15 49.79,56.15 X9.1
  Bottom 0.2: v68.2,73 68.6,72.6 70.6,72.6 71.2,73.2 112,73.2 113.6,71.6 113.6,60 112.6,59 112.6,56.6 v112.2,56.2 | X9.1 45.99,57.41 v44.8,58.6
A0  (via drill 0.4 pad 0.8)
  Top 0.2: X10.11 68.4,59 70.3,60.3 83.2,60.3 v83.4,60.5 | U1.24 90.95,58.4 88.1,58.4 v87.7,58.8
  Bottom 0.2: v83.4,60.5 83.4,60.1 85,58.5 85.4,58.5 86,58.5 87.4,58.5 v87.7,58.8
AD0
  Top 0.2: U1.32 87.5,53.05 84.25,49.8 73.7,49.8 67.6,43.7 67.6,15.4 67.8,15.2 R49.2
AD1
  Top 0.2: U1.33 87.75,52.55 86.8,51.6 85.05,49.9 84.45,49.3 73.9,49.3 68.1,43.5 68.1,17.3 70.4,15 74,15 74.4,14.6 R45.2
AD2
  Top 0.2: U1.34 87.95,52.05 84.7,48.8 74.1,48.8 68.6,43.3 68.6,17.6 70.6,15.6 75,15.6 76,14.6 R47.2
AD3
  Top 0.2: U1.35 88.2,51.55 84.9,48.25 74.25,48.25 69.1,43.1 69.1,17.9 70.8,16.2 75.2,16.2 75.8,15.6 R48.2
AD5
  Top 0.2: U1.40 92.55,47.95 89.7,45.1 77.8,45.1 76.9,44.2 71.6,44.2 70.1,42.7 70.1,18.5 71.2,17.4 77.4,17.4 77.8,17.8 81.5,17.8 84.9,14.4 84.9,11.4 87.8,8.5 R50.2
AD6  (via drill 0.4 pad 0.8)
  Top 0.2: U1.30 86.95,54.05 83.8,50.9 74.6,50.9 73.4,52.1 65.9,52.1 v65.7,51.9
  Bottom 0.2: 65.4,51.9 v65.7,51.9 65,51.9 64.59,52.31 X10.14
AD7  (via drill 0.4 pad 0.8)
  Top 0.2: R26.1 97.6,32.8 96.4,34 v96.4,36.4 C62.2 | U1.42 93.55,50.95 v93.6,51
  Bottom 0.2: v93.6,51 93.6,50.1 94.4,49.3 94.4,42.6 96.4,40.6 v96.4,36.4
AD_CLK  (via drill 0.4 pad 0.8)
  Top 0.2: R20.1 v61.2,29.6 | U1.45 95.05,48.05 95.5,47.6 95.5,46.1 93.5,44.1 78.3,44.1 76.3,42.1 75.8,41.6 v75.8,41.1
  Bottom 0.2: v61.2,29.6 61.8,29.6 62.4,30.2 62.4,32.6 63.4,33.6 65.6,33.6 67,35 67,40.1 67.6,40.7 74.9,40.7 75.2,40.7 75.4,40.7 v75.8,41.1
AD_DATA  (via drill 0.4 pad 0.8)
  Top 0.2: R19.1 v61.2,31 | v75.4,42.4 75.8,42.4 78,44.6 93.3,44.6 93.8,45.1 93.8,47.8 94.05,48.05 U1.43
  Bottom 0.2: v61.2,31 61.6,31 62,31.4 62,32.8 63.2,34 65.4,34 66.6,35.2 66.6,40.4 67.4,41.2 73.7,41.2 74,41.2 74.2,41.2 v75.4,42.4
AD_LE  (via drill 0.4 pad 0.8)
  Top 0.2: R18.1 v61.2,32.4 | v77,41.4 79.1,41.4 80.3,42.6 94.1,42.6 97,45.5 97,48.2 96.55,48.65 U1.48
  Bottom 0.2: v61.2,32.4 61.2,32.6 63,34.4 65.2,34.4 66.2,35.4 66.2,40.7 67.2,41.7 73.5,41.7 75,43.2 75.8,43.2 77,42 v77,41.4
CS  (via drill 0.4 pad 0.8)
  Top 0.2: U1.31 87.25,53.55 84.1,50.4 69.5,50.4 v69.3,50.6
  Bottom 0.2: X10.12 67.13,51.27 67.8,50.6 v69.3,50.6
D0  (via drill 0.4 pad 0.8)
  Top 0.2: v96.8,52.2 96.8,51.8 97.05,51.55 U1.2
  Bottom 0.2: v96.8,52.2 95.6,52.2 94.9,52.9 93,52.9 91.8,51.7 90,51.7 89.3,52.4 72.9,52.4 72.21,53.09 X10.8
D1  (via drill 0.4 pad 0.8)
  Top 0.2: X10.7 73.48,58.68 74.3,59.3 83.7,59.3 84,59 84.1,59 84.3,59 85.5,59 v85.9,59.4 | U1.13 96.55,59.45 v96.8,59.7
  Bottom 0.2: v85.9,59.4 86.2,59.7 v96.8,59.7
D2
  Top 0.2: U1.26 86.65,56.05 83,52.4 81.55,52.4 76.05,52.4 75.4,52.4 74.75,53.05 X10.6
D3  (via drill 0.4 pad 0.8)
  Top 0.2: U1.38 91.55,52.45 v91.4,52.6
  Bottom 0.2: v91.4,52.6 91.1,52.9 76.6,52.9 76.02,53.48 X10.5
D4
  Top 0.2: U1.18 94.05,57.25 93.3,56.5 92.5,56.5 91.3,56.5 89.9,57.9 83.6,57.9 83.2,58.3 80.3,58.3 79.85,57.85 79.85,56.4 79,55.55 78.41,55.55 X10.4
D5
  Top 0.2: X10.3 78.56,57.96 79.5,58.8 83.5,58.8 83.8,58.5 86.2,58.5 87.5,59.8 88.8,59.8 90,61 91.7,61 92.55,60.15 U1.21
D6  (via drill 0.4 pad 0.8)
  Top 0.2: U1.1 96.65,51.05 95.9,51.8 v95.9,53.1
  Bottom 0.2: X10.2 80.86,53.4 95.6,53.4 v95.9,53.1
D7
  Top 0.2: U1.11 96.45,56.05 95.8,55.4 93.8,55.4 93.2,56 91.1,56 89.7,57.4 81.53,57.4 X10.1
DG_STATUS  (via drill 0.4 pad 0.8)
  Top 0.2: U1.10 96.95,55.55 96.3,54.9 93.4,54.9 93,55.3 92.4,55.3 91.9,55.3 v91.3,54.7
  Bottom 0.2: X10.15 63.32,57.62 64.9,59.2 81.4,59.2 86.2,54.4 91,54.4 v91.3,54.7
EX_SIG
  Top 0.2: U1.27 90.15,55.55 90.5,55.2 90.5,50.6 90,50.1 88.3,50.1 85.3,47.1 77.1,47.1 76.6,46.6 75.7,46.6 75.1,47.2 73.9,47.2 69.6,42.9 69.6,18.2 71,16.8 R46.2
F_REF
  Top 0.2: R23.2 C26.2
GND  (via drill 0.4 pad 0.8, 1 pad 0.8)
  Top 0.2: 50.46,24.6 v51.2,24.6 | v54.2,27.2 53.87,26.87 | U3.9 v47.61,28.19 v47.6,28.2 47.62,28.22 U3.8 | v46.45,19.95 C5.1 | C1.1 v38,25.4 | C11.1 47.65,20.55 v47.8,20.4 | v45.6,17.8 C12.1 | C15.1 v49.6,16.4 | C9.1 v52.81,18.61 v52.8,18.6 | C10.1 v54.4,18 | C8.1 v55.8,18 | R1.2 v51.2,16.4 | C7.1 54.8,22 v55.6,22 | R17.1 62.2,25.45 v62.2,26.4 | 48.95,26.35 v49.2,26.6 | C3.1 v49.45,33.4 | 97.8,24.48 U4.2 | U4.11 97.8,24.48 | 97.8,24.48 U4.EP | C37.1 v104.2,25.8 | U4.8 96.83,27.2 v95.6,27.2 | U9.2 114,48.95 114,41.2 | 97.8,66.8 R29.1 | 97.8,66.8 X6.C1 97.2,68.8 92.2,68.8 | 92.2,68.8 X6.4 | 91.4,68.8 92.2,68.8 | 91.4,68.8 X6.5 | X6.C4 88.8,68.8 91.4,68.8 | v102.8,53.6 102.8,53.4 C46.1 101.2,53.05 U1.5 | v92.2,46 92.2,46.6 92.6,47 C47.1 93.05,47.05 U1.41 | C61.1 v105.6,48.8 | v99.2,67.4 97.8,67.4 97.8,66.8 | v99.2,72.2 97.2,72.2 X6.C2 | v86.8,72.2 88.8,72.2 X6.C3 | C62.1 93.8,38.58 S2.7 | C66.1 58.8,13.56 S1.25 | U2.4 U2.2 | U7.2 U7.4 | U12.4 U12.2
  Top 0.3: R16.1 v22.4,16.4 | C21.1 v46.2,38.6 | v39.8,34.6 C20.1 | v44.95,26.8 45.4,26.35 U3.11 48.95,26.35 | U3.18 48.96,24.36 v49.2,24.6 | U3.21 50.46,24.6 | U3.27 54.35,24.85 v54.6,24.6 | C6.1 v41.6,18.8 | C2.1 v46,30.6 | C4.1 v58.4,25.4 | U3.31 53.85,26.85 v54.2,27.2 | R5.1 v52.6,36.4 | C13.1 v54.4,36.4 | R11.1 v35,20.2 | L7.5 39.67,16.2 | U4.2 101,24.48 v101,24.2 101,23.82 U4.1 | U4.11 94.6,24.48 v94.6,24.2 94.6,23.82 U4.12 | C39.1 v93.4,23.6 | C38.1 v101.8,30.6 | C40.1 v93.4,30.6 | R25.1 v89.4,25.15 | C36.1 v99.6,30.6 | U2C.2 73.19,23.45 U2B.7 72.8,23.78 72.8,23.8 72.6,23.8 C44.1 | v76.8,31.4 U7.2 | C43.1 61.39,34.4 v61.6,34.4 | C42.1 61.39,39.8 v61.6,39.8 | C41.1 v60.4,41.2 | U2.2 v56.4,39.6 | U12.2 v105.8,59.8 | C59.1 v111.6,61.2 | C60.1 v111,57.4 | C23.1 20.6,43.74 S1.27 | VT1.2 15.86,44 S1.28 | VT2.2 23.46,43.06 24.44,44.04 S1.23
  Top 0.4: v12.8,16.4 R14.1 | v7.8,22.2 C33.2 | C29.2 v14.2,23 | C34.2 v20.4,22.2 | C32.2 v23.8,22.2 | C22.2 v30,23 | C31.2 v35.4,23.2 | C30.2 v39.8,31.6 | R13.1 v29.6,16.2
  Top 0.5: L13.5 v41.93,37.2 | 39.67,16.2 v40.6,16.2 | R24.1 v92.8,17.8 | C35.2 v98.6,18.4 | v2.6,59 2.6,57.91 VD3.A 8.6,57.91 v8.6,59 | v8.6,60.47 C57.1 12,60.47 v12,62 | U11.3 v18.4,62.4 U11.6 | 25,60.6 C58.1 | 25,60.6 v23,60.6 21.75,60.6 U11.5 | 25,60.6 v27.2,60.6 | R36.1 27.19,44.04 S1.23
  Bottom 0.2: v54.6,24.6 54.8,24.6 | v54.2,27.2 54.4,27.2 | v47.6,28.2 47.4,28.2 | v41.6,18.8 41.8,18.8 | v46.45,19.95 46.45,20.15 | v38,25.4 38,25.6 | v47.8,20.4 48,20.4 | 45.6,17.6 v45.6,17.8 | v49.6,16.4 49.6,16.2 | v52.8,18.6 52.8,18.4 | v54.4,18 54.4,17.8 | v55.8,18 55.8,17.8 | v51.2,16.4 51.2,16.2 | v55.6,22 55.8,22 | v58.4,25.4 58.6,25.4 | v62.2,26.4 62.2,26.8 | v52.6,36.4 52.6,36.6 | v54.4,36.4 54.4,36.6 | v49.45,33.4 49.45,33.6 | v92.8,17.8 92.4,17.8 | v98.6,18.4 98.6,18.6 | v101,24.2 101.2,24.2 | v94.6,24.2 94.4,24.2 | v93.4,23.6 93.4,23.4 | v104.2,25.8 104.6,25.8 | v101.8,30.6 101.8,30.4 | v95.6,27.2 95.6,28 | v93.4,30.6 93.4,30.4 | v89.4,25.15 89.3,25.15 | v99.6,30.6 99.6,30.8 | v102.8,53.6 103.4,53.6 | v92.2,46 92.4,46 | v105.6,48.8 105.6,48.6
  Bottom 0.3: v22.4,16.4 22.6,16.4 | 12.4,16.4 v12.8,16.4 | 7.4,22.2 v7.8,22.2 | v14.2,23 14.2,23.2 | v20.4,22.2 21,22.2 | v30,23 30,23.2 | v35.4,23.2 35.4,23.6 | v46.2,38.6 46.4,38.6 | v39.8,34.6 39.8,34.2 | v39.8,31.6 39.8,31.8 | v41.93,37.2 42.4,37.2 | v46,30.6 46,30 | v29.6,16.2 29.4,16.2 | v35,20.2 35,20.6 | v40.6,16.2 41,16.2 | v76.8,31.4 76.8,31.6 | v61.6,34.4 62,34.4 | v61.6,39.8 62,39.8 | v60.4,41.2 60.8,41.2 | v56.4,39.6 56.8,39.6 | v105.8,59.8 106.2,59.8 | v111.6,61.2 111.8,61.2 | v111,57.4 C60.1
  Bottom 0.4: v23.8,22.2 23.4,22.2
  Bottom 0.5: v2.6,59 2.6,59.6 | v8.6,59 v8.6,60.47 | 11.6,62 v12,62 12,63.4 | v18.4,62.4 16.8,62.4 | v23,60.6 23,61.6
  other vias: 51.2,26.6 50.2,25.6 97.8,24.8 27.6,52.8 34.6,61.4 37.8,61.4 48.3,64.7 53.2,58.4 45.4,53.4 40.3,49.9 87,67.8 72.4,42.7 72.4,39.6 79.3,37.8 80.3,40.3 51.9,71.6 39.1,73.5 65.7,72.2 65.9,61.1 56.3,61.1 112.1,46.1 53.2,7.5 64.9,12.1 58,1.3 1.7,73.3 11.2,73.2 25.4,73.3 22.9,73.3 13.7,73.2
  pour Bottom (isolate 0.3): 114.4,74.4 0.6,74.4 0.6,0.6 12.2,0.6 12.2,4.6 40,4.6 40,0.6 90.4,0.6 90.4,4.6 103.6,4.6 103.6,0.6 114.4,0.6
  pour Top (isolate 0.3): 0.6,0.6 0.6,74.4 66.4,74.4 66.4,47 114.4,47 114.4,0.6 103.6,0.6 103.6,4.6 90.4,4.6 90.4,0.6 57.1,0.6 57.1,2.8 42.6,2.8 42.6,0.6 40,0.6 40,4.6 12.2,4.6 12.2,0.6
KONTRAST
  Top 0.2: X10.17 60.78,59.9 | 60.78,59.9 R41.1 | 60.78,59.9 R44.2
LOC+3,3V  (via drill 0.4 pad 0.8)
  Top 0.2: R9.1 R10.1 v38.2,28.6 38,28.4 C1.2 | C4.2 55.95,25.35 | C3.2 U3.6 | 49.4,31.8 49.45,31.75
  Top 0.3: U3.10 46.65,26.85 v46.2,27.3 46,27.5 C2.2 46,28.8 46.2,29 46.8,29 47.2,29.4 v47.2,31.8 | C5.2 v46.45,23.2 46.45,23.6 46.7,23.85 U3.16 | C5.2 47.15,22.35 47.8,23 U3.17 | C5.2 45.35,22.35 45,22 45,20.4 44.6,20 R7.1 | R7.1 43.8,19 C6.2 | R8.1 R7.1 | R3.2 57,24 56.8,24.2 56.8,25.4 | 56.8,25.4 C4.2 | v56.8,26.4 56.8,25.4 | 55.95,25.35 U3.28 | U3.32 52.8,27.6 53.4,28.2 v55.2,28.2 | 52.6,31.8 v55.2,31.8 56.2,31.8 57.2,32.8 57.2,35 57.6,35.4 L1.2 59.41,36.26 C43.2 | 52.6,31.8 R2.2 | v48.6,31.8 49.4,31.8 52.6,31.8 | 49.45,31.75 C3.2
  Bottom 0.2: v46.45,23.2 46.45,27.05 v46.2,27.3 44.9,28.6 v38.2,28.6
  Bottom 0.3: v56.8,26.4 56.8,27 55.6,28.2 v55.2,28.2 v55.2,31.8 | v47.2,31.8 v48.6,31.8
N$1
  Top 0.2: R18.2 58.25,32.4 56.6,30.75 54.7,30.75 53.65,29.7 51.5,29.7 50.95,29.15 U3.3
N$2
  Top 0.2: C8.2 55.8,21 55.6,21.2 54.2,21.2 54,21.4 54,22 53.8,22.2 C7.2 52.2,22.2 51.95,22.45 U3.24
N$3
  Top 0.2: C10.2 53,20.4 52.8,20.6 C9.2 52.2,21 51.45,21.75 U3.23
N$4
  Top 0.2: C12.2 47.8,18.8 49.25,20.25 C11.2 49.45,21.65 U3.19
N$5
  Top 0.2: R1.1 51.2,21.2 50.95,21.45 U3.22
N$6
  Top 0.2: R7.2 43.8,23
  Top 0.3: U3.15 45.95,24.35 44.6,23 43.8,23 C19.2
N$7
  Top 0.2: R2.1 52.6,30.45 52.35,30.2 51.3,30.2 50.45,29.35 U3.4
N$8
  Top 0.2: U3.26 53.7,24.35 54.25,23.8 55.2,23.8 55.4,24 R3.1
N$9
  Top 0.2: U3.20 49.95,19.97 49.96,19.96 49.6,19.6 C15.2 49.6,18.2 49.8,18 52,18 53,17 56.6,17 58,18.2 58,22.6 59.4,24 59.4,33.6 59,34 R6.1
N$10
  Top 0.2: R4.1 C14.1 R5.2
N$11
  Top 0.2: R4.2 51,30.6 49.95,29.55 U3.5
N$12
  Top 0.2: U3.7 48.96,29.24 47.9,30.3 47.9,33.5 50,35.6 C14.2 51,35 51.2,34.8 54.2,34.8 54.4,34.6 C13.2 R6.2
N$13
  Top 0.2: C18.2 42.6,24.4 42.4,24.2 R8.2
  Top 0.3: U3.14 45.05,24.85 44.6,24.4 C18.2
N$14
  Top 0.2: R19.2 58,31 57.15,30.15 54.9,30.15 53.95,29.2 51.7,29.2 51.45,28.95 U3.2
N$15
  Top 0.2: R20.2 55.15,29.6 54.25,28.7 52,28.7 51.95,28.65 U3.1
N$16
  Top 0.2: 42.4,27.2 R9.2
  Top 0.3: U3.13 44.25,25.35 arc-90 42.4,27.2 C17.2
N$17
  Top 0.2: C16.2 43.8,28.4 43.6,28.6 R10.2
  Top 0.3: U3.12 44.95,25.85 arc-90 43.8,27 C16.2
N$18
  Top 0.5: L7.3 37.13,21.93 arc-90 39.6,24.4 C18.1
N$19
  Top 0.5: L7.1 39.67,21.87 arc-90 40.8,23 C19.1
N$20
  Top 0.4: L13.3 44.47,30.07 C16.1
N$21
  Top 0.4: L13.1 41.93,29.87 C17.1
N$22
  Top 0.3: 36.87,16.2 L7.4
  Top 0.5: 36.87,16.2 R12.2 35,16.2 R11.2
N$23
  Top 0.5: X1.A R12.1 R13.2
N$24
  Top 0.5: L3.1 C21.2 43.8,37.8 44.47,37.13 L13.4
N$25
  Top 0.5: L4.1 C20.2 38.2,37.2 arc-90 39.6,38.6 L3.2
N$26
  Top 0.5: REL1.8 C30.1 L4.2
N$27
  Top 0.5: X2.A R15.1 R16.2
N$28
  Top 0.5: R15.2 R14.2 15.2,17.2 arc90 14.2,18.2 7.6,18.2 arc-90 5.6,20.2 5.6,29 arc-90 7.2,30.6 REL2.3
N$29
  Top 0.5: REL2.2 REL2.9
N$30
  Top 0.4: REL2.4 10.94,28.06 arc-90 12,27 L12.2 C33.1
N$31
  Top 0.4: REL2.7 17.86,28.06 arc90 16.4,26.6 L10.1 C34.1
N$32
  Top 0.5: REL2.8 REL1.3
N$33
  Top 0.4: REL1.4 26.54,28.06 arc-90 27.8,26.8 L11.2 C32.1
N$34
  Top 0.4: L12.1 C29.1 L10.2
N$35
  Top 0.4: L11.1 C22.1 L9.2
N$36
  Top 0.4: REL1.7 33.66,28.06 arc90 32.2,26.6 L9.1 C31.1
N$37
  Top 0.5: REL1.2 REL1.9
N$38
  Top 0.3: REL1.10 33.12,35.68 29.82,38.98 VT2.3
N$39
  Top 0.3: REL2.10 17.52,35.68 16.8,36.4 16.8,38.96 VT1.3
N$40
  Top 0.2: C25.1 58.2,26.8 57.8,27.2 56.15,27.2 54.8,25.85 U3.29
N$41
  Top 0.2: C25.2 60.25,26.8 R17.2 C26.1
N$42
  Top 0.2: U3.25 53.5,23.85 54.05,23.3 55.1,23.3 55.5,22.9 56.5,22.9 57.2,22.2 R21.2
N$43
  Top 0.2: R22.2 58.2,28.2 57.8,27.8 56,27.8 54.55,26.35 U3.30
N$44  (via drill 0.4 pad 0.8)
  Top 0.3: v60.2,17.8 60.25,18.4 R23.1 | U2B.8 80.81,23.45 U2C.3
  Bottom 0.3: U2B.8 U2A.8 80.81,19.81 78.8,17.8 71.8,17.8 71,17.8 70.1,18.7 61.1,18.7 v60.2,17.8
N$45
  Top 0.5: X3.A C27.2
N$46
  Top 0.5: R24.2 C27.1 C28.2
N$47
  Top 0.3: U4.14 97.47,21.88 97,21.4 C28.1
N$48
  Top 0.3: U4.15 98.12,21.88 98.6,21.4 C35.1
N$49
  Top 0.2: U4.5 98.78,27.98 99,28.2 C36.2
N$50
  Top 0.2: U4.10 91.8,25.12 R25.2
N$51
  Top 0.2: U4.7 97.47,28.2 R26.2 98.12,28.2 U4.6
N$52
  Top 0.3: C42.2 57.6,38.4 L1.1 55.23,38.14 U2.1
N$53
  Top 0.2: X6.3 93,64.8 92.6,64.4 92.6,64.2 | 92.6,64.2 R27.2 | R31.2 92.6,64.2
N$54
  Top 0.2: X6.2 93.8,64.8 94.2,64.4 R28.2
N$55
  Top 0.2: X6.1 94.6,65.6 96,64.2 R30.1
N$56
  Top 0.2: U1.19 93.55,60.35 94.2,61 R28.1
N$57
  Top 0.2: U1.20 93.05,60.35 92.6,60.8 R27.1
N$58
  Top 0.2: T1.3 87,64.2 R31.1
N$59
  Top 0.2: 86.06,61.2 T1.1 | 86.06,61.2 R33.2 | 86.06,61.2 86.06,60.54 86.3,60.3 88.5,60.3 90,61.8 R32.1
N$60
  Top 0.2: U1.6 99.55,53.55 100.2,54.2 102,54.2 103.2,55.4 C48.1
N$61
  Top 0.2: R34.2 C48.2
N$62
  Top 0.2: R34.1 107.6,48.95 U9.3
N$63
  Top 0.3: U10.1 31.41,58.01 31.2,57.8 C50.1
N$64
  Top 0.3: U10.3 31.53,55.47 31.19,55.81 C50.2
N$65
  Top 0.3: U10.4 C51.2
N$66
  Top 0.3: U10.5 31.93,52.93 31.2,52.2 C51.1
N$67
  Top 0.3: U10.6 32.06,51.66 30.99,50.59 C52.2
N$68
  Top 0.3: U10.2 32.91,56.8 28.8,56.8 28.19,56.19 C53.2
N$69  (via drill 0.4 pad 0.8)
  Top 0.2: C66.2 R21.1 58.8,18.7 v59,18.7 | v71.3,19.3 70.8,19.8 70.8,42.7 71.8,43.7 74.1,43.7 74.6,43.2 74.6,41.1 75.3,40.4 77.3,40.4 77.8,40.9 79.3,40.9 80.5,42.1 94.3,42.1 97.5,45.3 97.5,48.2 98.5,49.2 v98.5,49.8 | v94.2,56.2 94.55,56.55 U1.17
  Bottom 0.2: v59,18.7 59.6,19.3 v71.3,19.3 | v94.2,56.2 94.2,56.1 95,55.3 96.2,55.3 99.1,52.4 99.1,50.4 v98.5,49.8
N$70  (via drill 0.4 pad 0.8)
  Top 0.2: R22.1 60.6,28.2 61,27.8 61,24.4 61.4,24 61.4,16.4 v61,16
  Bottom 0.2: v61,16 60.2,16 59.2,15 JP1.1
N$71
  Top 0.2: VT1.1 18.38,41.02 19.4,40 R39.2
N$72
  Top 0.2: VT2.1 25.39,41.2 R40.2
N$73
  Top 0.5: VD3.K 5.8,52 L5.1 14.2,52 16.72,54.52 U11.2
N$74
  Top 0.3: U11.4 20.08,56.88 18.8,55.6 18.8,48.4 19.6,47.6 R36.2 25.21,49.41 C56.1 R35.1
N$75  (via drill 0.4 pad 0.8)
  Top 0.2: U1.15 95.55,57.35 96,56.9 v96.5,56.9 | R43.1 103.5,47.57 JP2.2
  Bottom 0.2: v96.5,56.9 96.5,56.4 100.1,52.8 100.1,47.8 100.33,47.57 JP2.2
N$76  (via drill 0.4 pad 0.8)
  Top 0.2: U1.16 95.05,56.55 v95.4,56.2 | R42.1 103.5,45.03 JP2.3
  Bottom 0.2: JP2.3 100.17,45.03 99.6,45.6 99.6,52.6 96.3,55.9 95.7,55.9 v95.4,56.2
N$77  (via drill 0.4 pad 0.8)
  Top 0.2: U1.9 97.25,55.05 96.6,54.4 92.6,54.4 v92.5,54.3
  Bottom 0.2: X10.13 65.86,57.86 66.7,58.7 81.2,58.7 86,53.9 91.7,53.9 92.1,54.3 v92.5,54.3
N$78
  Top 0.2: X4.4 83.2,9 83.9,9.7 83.9,9.85 83.9,10 83.9,13.95 82.25,15.6 R48.1
N$79
  Top 0.2: X4.3 79,9 76,12 R47.1
N$80
  Top 0.2: X5.4 71.4,9 74.4,12 R45.1
N$81
  Top 0.2: X5.3 66.6,10.3 66.6,14.2 66.8,14.4 R49.1
N$82
  Top 0.2: X5.6 70.9,4.7 72.2,3.4 77.8,3.4 79,4.6 80.6,4.6 80.9,4.3 | 80.9,4.3 81.8,3.4 85.8,3.4 86.8,4.4 86.8,8.2 86.8,8.45 86.8,8.8 84.4,11.2 84.4,14.2 81.8,16.8 R46.1 | X4.6 82.5,5.9 80.9,4.3
N$83  (via drill 0.4 pad 0.8)
  Top 0.2: R50.1 87.8,4.6 86,2.8 80.4,2.8 80.2,3 v79.8,3.4 79.2,2.8 71.2,2.8 67.9,6.1 X5.5
  Bottom 0.2: X4.5 79.5,3.7 v79.8,3.4
OUT  (via drill 0.4 pad 0.8)
  Top 0.4: U5.2 55.9,9.89 C68.2 56.13,8.2 61.5,8.2 63.3,10 v64.6,10
  Bottom 0.4: 66.8,11 65.6,11 v64.6,10 | X4.1 77.4,11 73.1,15.3 68.3,15.3 66.8,13.8 66.8,11 | 66.8,11 X5.1
RD  (via drill 0.4 pad 0.8)
  Top 0.2: U1.12 97.8,56.55 v97.8,58.5 | X10.9 70.94,59.34 71.9,59.8 v84.8,59.8
  Bottom 0.2: v97.8,58.5 97.8,59.9 97.2,60.5 96.1,60.5 95.8,60.2 85.8,60.2 85.6,60.2 85.2,60.2 v84.8,59.8
RXD1  (via drill 0.4 pad 0.8)
  Top 0.2: v78.7,43.2 79.1,43.6 93.7,43.6 96,45.9 96,47.8 95.55,48.25 U1.46 | U10.12 43.47,52.93 45,51.4 45,48.8 45.6,48.2 67.4,48.2 v67.6,48
  Bottom 0.2: v67.6,48 68.3,48 68.9,47.4 68.9,46.7 71.4,44.2 76.2,44.2 77.2,43.2 v78.7,43.2
SWCLK
  Top 0.2: X9.6 52.07,52.33 52.6,51.8 52.6,50.2 53.6,49.2 59.7,49.2 61.9,51.4 62.1,51.6 63.1,52.6 73.6,52.6 74.8,51.4 83.6,51.4 86.75,54.55 U1.29
SWDIO  (via drill 0.4 pad 0.8)
  Top 0.2: U1.39 92.05,48.15 89.5,45.6 89.3,45.6 73.6,45.6 v73,45 | v68.4,48.9 67.2,48.9 67,48.7 53.2,48.7 52.11,49.79 X9.8
  Bottom 0.2: v73,45 72.7,44.7 71.6,44.7 69.4,46.9 69.4,47.4 69.4,47.9 v68.4,48.9
SWO
  Top 0.2: U1.28 86.45,55.05 83.3,51.9 75.1,51.9 73.9,53.1 62.8,53.1 61.9,52.2 61.6,51.9 59.4,49.7 53.8,49.7 53.1,50.4 53.1,54.1 52.33,54.87 X9.4
TIEFP1  (via drill 0.4 pad 0.8)
  Top 0.2: R39.1 33.4,40 34,40.6 v34,41.4 | v37.4,47.6 38.3,46.7 66.2,46.7 67.5,45.4 68.6,45.4 70.2,47 v70.2,47.5 | v74.6,46.4 74.9,46.1 88.6,46.1 89.3,46.1 91.05,47.85 U1.37
  Bottom 0.2: v34,41.4 34,42.2 33.7,42.5 33.7,45.4 35.9,47.6 v37.4,47.6 | v74.6,46.4 73.5,47.5 v70.2,47.5
TIEFP2  (via drill 0.4 pad 0.8)
  Top 0.2: R40.1 31.8,41.2 v32.2,41.6 | v38.4,48.6 39.4,48.6 40.8,47.2 66.4,47.2 67.6,46 68.5,46 68.9,46.4 68.9,47.5 69.8,48.4 v71,48.4 | v76.1,47.4 76.4,47.7 85.1,47.7 88.45,51.05 U1.36
  Bottom 0.2: v32.2,41.6 33.2,42.6 33.2,45.6 36.2,48.6 v38.4,48.6 | v71,48.4 71.4,48 75.5,48 v76.1,47.4
TXD1  (via drill 0.4 pad 0.8)
  Top 0.2: U10.11 43.94,51.66 44.5,51.1 44.5,48.5 45.3,47.7 66.6,47.7 67.4,46.9 v68,46.9 | v77.8,42.3 79.2,42.3 80,43.1 93.9,43.1 96.5,45.7 96.5,48 96.05,48.45 U1.47
  Bottom 0.2: v68,46.9 71.2,43.7 76,43.7 77.4,42.3 v77.8,42.3
USB_CONN
  Top 0.2: U1.22 92.05,59.95 91.8,60.2 R32.2
USB_VBUS
  Top 0.2: U1.14 96.05,61.75 R30.2 R29.2
V24_RXD
  Top 0.3: U10.13 43.8,54.2 46.6,57 46.6,65.4 49.4,68.2 49.4,71 48.73,71.67 X8.1
  Bottom 0.3: CON1.2 69.99,68.41 68.6,69.8 50.8,69.8 48.93,71.67 X8.1
V24_TXD
  Top 0.3: U10.14 44.07,55.47 45.94,57.34 45.94,65.74 47.54,67.34 X8.2
  Bottom 0.3: X8.2 66.07,69.13 67.2,68 CON1.3
WR
  Top 0.2: X10.10 70.94,55.7 75.6,55.7 76,55.3 76,53.6 76.7,52.9 79.8,52.9 81.9,52.9 82.8,52.9 86.45,56.55 U1.25

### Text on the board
Top: GF-4350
